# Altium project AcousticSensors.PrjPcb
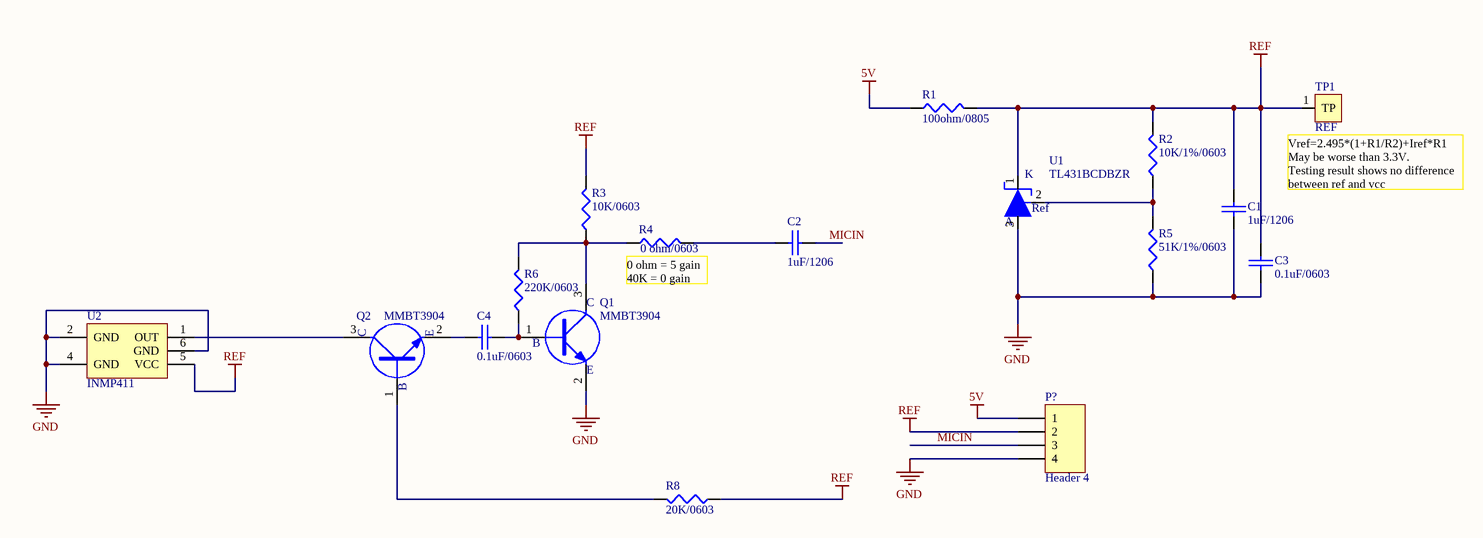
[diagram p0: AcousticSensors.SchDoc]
1 sheet, 17 parts. Net scope: global (net labels, ports and power ports of the same name join across sheets).
Board file: AcousticSensors.PcbDoc

## Sheet AcousticSensors.SchDoc
size A4

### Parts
C1  1uF/1206  [TAN_A]
C2  1uF/1206  [TAN_A]
C3  0.1uF/0603  [C0603]
C4  0.1uF/0603  [C0603]
P?  Header 4  [HDR1X4]
Q1  MMBT3904  [SOT-23]
Q2  MMBT3904  [SOT-23]
R1  100ohm/0805  [R0603]
R2  10K/1%/0603  [R0603]
R3  10K/0603  [R0603]
R4  0 ohm/0603  [R0603]
R5  51K/1%/0603  [R0603]
R6  220K/0603  [R0603]
R8  20K/0603  [R0603]
TP1  REF  [TP]
U1  TL431BCDBZR  [SOT-23]
U2  INMP411  [INMP411]

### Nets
5V: P?.1 R1.1
GND: C1.2 C3.2 P?.4 Q1.2(E) R5.1 U1.3(A) U2.2(GND) U2.4(GND) U2.6(GND)
REF: C1.1 C3.1 P?.2 R1.2 R2.2 R3.2 R8.1 TP1.1(TP) U1.1(K) U2.5(VCC)
MICIN: C2.1 P?.3
NetC2_2: C2.2 R4.2
NetC4_1: C4.1 Q1.1(B) R6.1
NetC4_2: C4.2 Q2.2(E)
NetQ1_3: Q1.3(C) R3.1 R4.1 R6.2
NetQ2_1: Q2.1(B) R8.2
NetQ2_3: Q2.3(C) U2.1(OUT)
NetR2_1: R2.1 R5.2 U1.2(REF)

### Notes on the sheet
- (near TP1) Vref=2.495*(1+R1/R2)+Iref*R1
  May be worse than 3.3V.
  Testing result shows no difference
  between ref and vcc
- (near R4) 0 ohm = 5 gain
  40K = 0 gain

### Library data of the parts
C1-C4 = C
P? = Header 4: Header, 4-Pin
Q1 Q2 = MMBT3904: NPN Transistor
R1-R6 R8 = RES
TP1 = Testpoint
U1 = TL431CDBZR: CAN NOT BE MFDT or MSDT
